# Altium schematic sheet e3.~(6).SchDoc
size custom portrait; Address1: Address1; Address2: Address2; Address3: Address3; Address4: Address4; SheetNumber: 1; SheetTotal: 1; Scale: 1:1; Разраб.: Иванов; Обозначение документа: АБВГ.123456.001Э3; Пров.: Петров; Утв.: Сидоров; Наименование организации: ОАО "Ваша фирма"; Перв. применение: АБВГ.123456.000; Наименование изделия 1: Плата; Наименование изделия 2: Схема электрическая; Наименование изделия 3: принципиальная; Нач. отд.: Нач. отд.; Фамилия нач. отд.: Сидоров
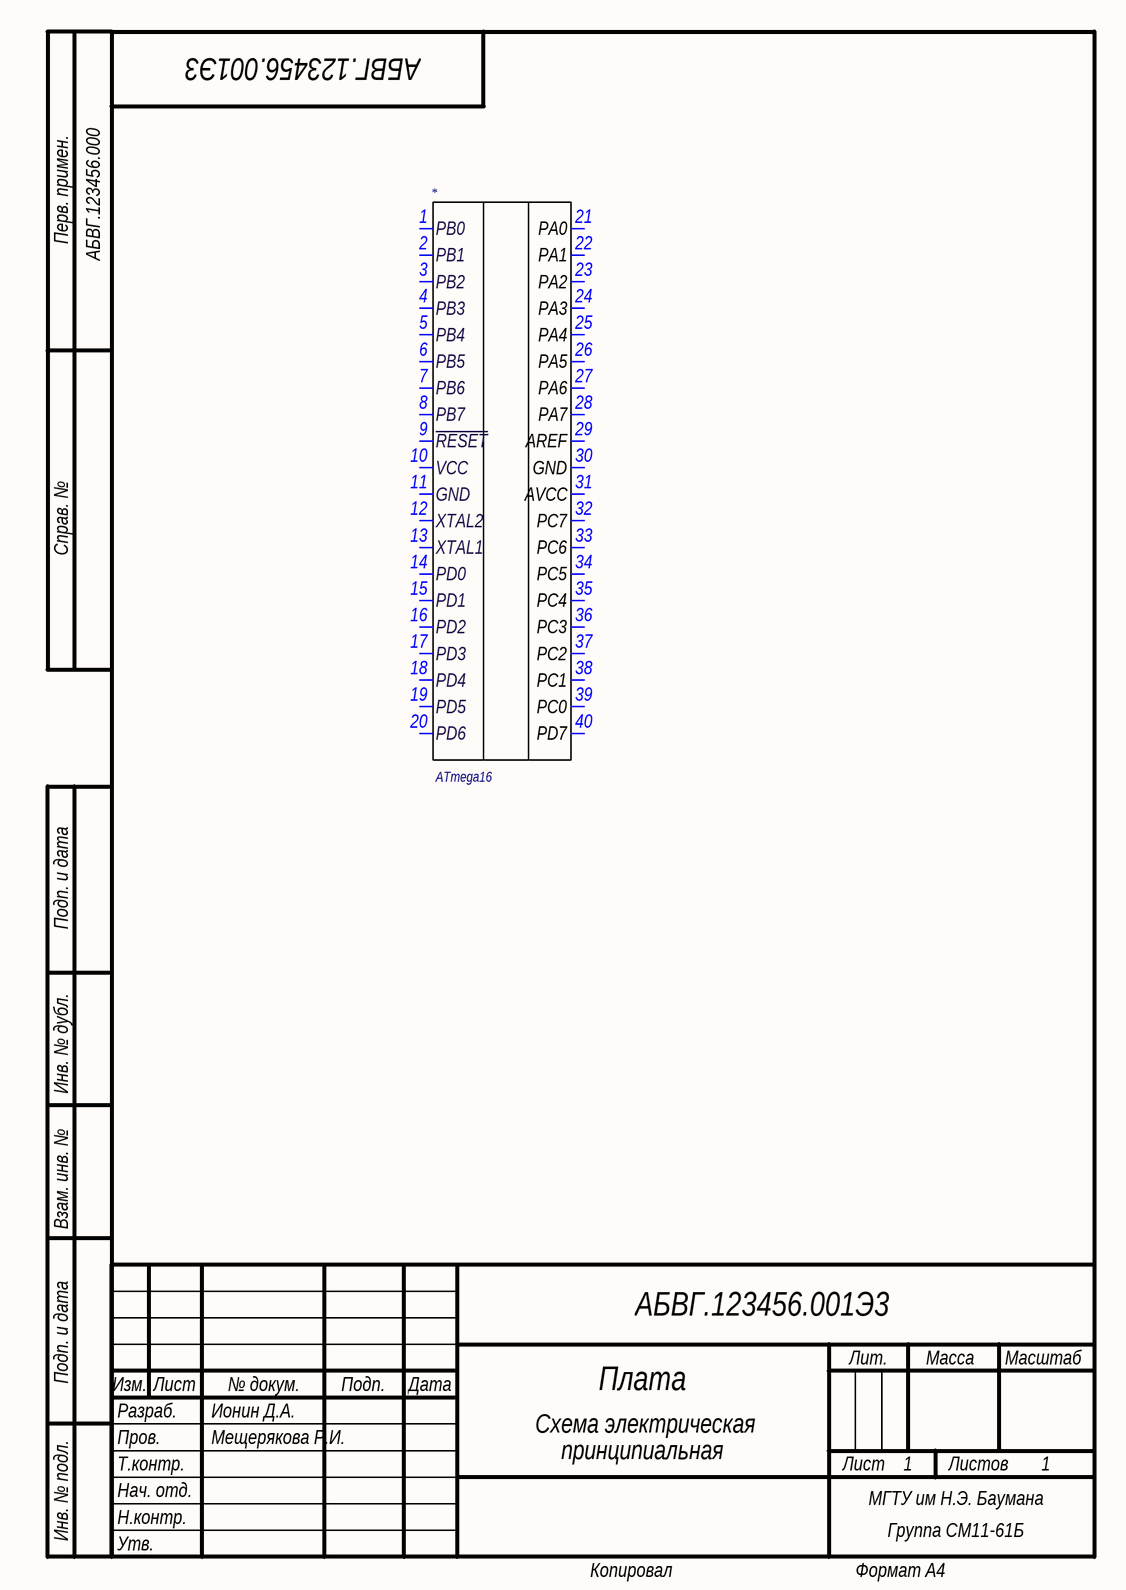
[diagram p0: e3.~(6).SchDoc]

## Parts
*  ATmega16

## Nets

Not connected (* = marked no-connect by the designer): * 1(PB0) 2(PB1) 3(PB2) 4(PB3) 5(PB4) 6(PB5) 7(PB6) 8(PB7) 9(~{RESET}) 10(VCC) 11(GND) 12(XTAL2) 13(XTAL1) 14(PD0) 15(PD1) 16(PD2) 17(PD3) 18(PD4) 19(PD5) 20(PD6) 21(PA0) 22(PA1) 23(PA2) 24(PA3) 25(PA4) 26(PA5) 27(PA6) 28(PA7) 29(AREF) 30(GND) 31(AVCC) 32(PC7) 33(PC6) 34(PC5) 35(PC4) 36(PC3) 37(PC2) 38(PC1) 39(PC0) 40(PD7)

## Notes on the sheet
- Перв. примен.
- Справ. №
- Подп. и дата
- Инв. № дубл.
- Взам. инв. №
- Разраб.
- Изм.
- Лист
- Ионин Д.А.
- № докум.
- Подп.
- Дата
- Лит.
- Масса
- Масштаб
- Пров.
- Т.контр.
- Мещерякова Р.И.
- Листов
- Инв. № подл.
- Утв.
- Н.контр.
- МГТУ им Н.Э. Баумана
- Группа СМ11-61Б
- Копировал
- Формат А4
